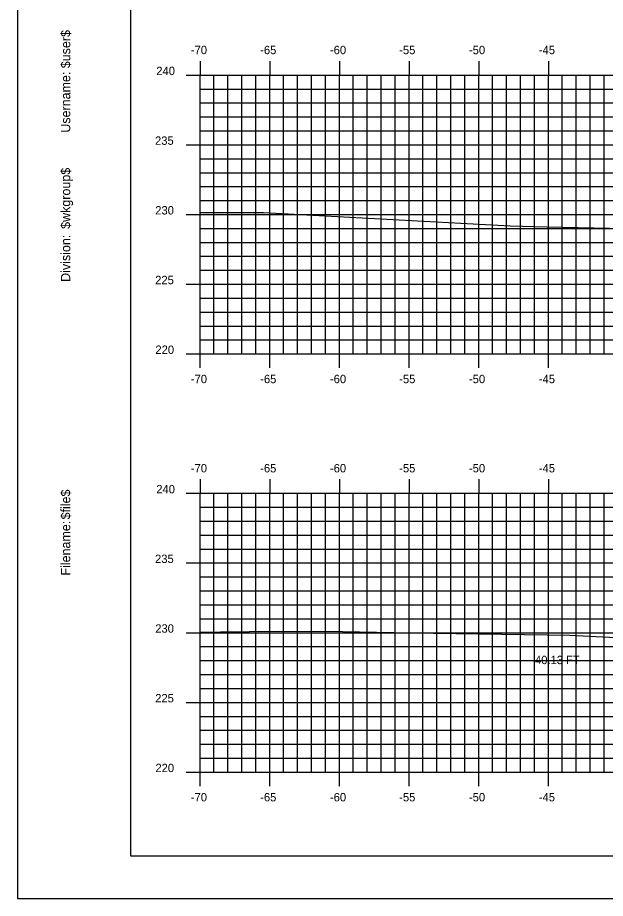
# Model space of a CAD drawing. Extents: x 1137211 to 1137381, y 608981 to 609091.
# Drawn here: x 1137210.8 to 1137253, y 608981.3 to 609044.5 of the extents above; entities that cross this region are included whole.
import ezdxf

# ---------------------------------------------------------------- set-up
doc = ezdxf.new("R2010")
doc.units = 0
for name, color, linetype in [('BORDER', 7, 'Continuous'), ('D_Text_Standard', 7, 'Continuous'), ('H_V ANNOTATION', 7, 'Continuous'), ('MAJOR', 7, 'Continuous'), ('MINOR', 7, 'Continuous'), ('PLOT BOUNDARY', 7, 'Continuous'), ('S_Roadway_Centerline', 7, 'Continuous')]:
    doc.layers.add(name, color=color, linetype=linetype)

msp = doc.modelspace()

# ---------------------------------------------------------------- linework, layer by layer
at = {"layer": 'BORDER'}
msp.add_lwpolyline([(1137218.897, 608984.335), (1137378.897, 608984.335), (1137378.897, 609089.335), (1137218.897, 609089.335)], close=True, dxfattribs=at)
at = {"layer": 'MAJOR'}
for p, q in [((1137223.896, 609041.337), (1137223.896, 609040.335)), ((1137228.896, 609041.337), (1137228.896, 609040.335)), ((1137233.896, 609041.337), (1137233.896, 609040.335)), ((1137238.896, 609041.337), (1137238.896, 609040.335)), ((1137243.896, 609041.337), (1137243.896, 609040.335)), ((1137248.896, 609041.337), (1137248.896, 609040.335)), ((1137222.894, 609040.335), (1137223.896, 609040.335)), ((1137223.896, 609040.335), (1137363.896, 609040.335)), ((1137223.896, 609020.335), (1137223.896, 609040.335)), ((1137223.896, 609020.335), (1137223.896, 609040.335)), ((1137223.896, 609040.335), (1137363.896, 609040.335)), ((1137228.896, 609020.335), (1137228.896, 609040.335)), ((1137233.896, 609020.335), (1137233.896, 609040.335)), ((1137238.896, 609020.335), (1137238.896, 609040.335)), ((1137243.896, 609020.335), (1137243.896, 609040.335)), ((1137248.896, 609020.335), (1137248.896, 609040.335)), ((1137222.894, 609035.335), (1137223.896, 609035.335)), ((1137223.896, 609035.335), (1137363.896, 609035.335)), ((1137222.894, 609030.335), (1137223.896, 609030.335)), ((1137223.896, 609030.335), (1137363.896, 609030.335)), ((1137222.894, 609025.335), (1137223.896, 609025.335)), ((1137223.896, 609025.335), (1137363.896, 609025.335)), ((1137222.894, 609020.335), (1137223.896, 609020.335)), ((1137223.896, 609020.335), (1137363.896, 609020.335)), ((1137223.896, 609020.335), (1137363.896, 609020.335)), ((1137223.896, 609019.333), (1137223.896, 609020.335)), ((1137228.896, 609019.333), (1137228.896, 609020.335)), ((1137233.896, 609019.333), (1137233.896, 609020.335)), ((1137238.896, 609019.333), (1137238.896, 609020.335)), ((1137243.896, 609019.333), (1137243.896, 609020.335)), ((1137248.896, 609019.333), (1137248.896, 609020.335)), ((1137223.896, 609011.337), (1137223.896, 609010.335)), ((1137228.896, 609011.337), (1137228.896, 609010.335)), ((1137233.896, 609011.337), (1137233.896, 609010.335)), ((1137238.896, 609011.337), (1137238.896, 609010.335)), ((1137243.896, 609011.337), (1137243.896, 609010.335)), ((1137248.896, 609011.337), (1137248.896, 609010.335)), ((1137222.894, 609010.335), (1137223.896, 609010.335)), ((1137223.896, 609010.335), (1137363.896, 609010.335)), ((1137223.896, 608990.335), (1137223.896, 609010.335)), ((1137223.896, 608990.335), (1137223.896, 609010.335)), ((1137223.896, 609010.335), (1137363.896, 609010.335)), ((1137228.896, 608990.335), (1137228.896, 609010.335)), ((1137233.896, 608990.335), (1137233.896, 609010.335)), ((1137238.896, 608990.335), (1137238.896, 609010.335)), ((1137243.896, 608990.335), (1137243.896, 609010.335)), ((1137248.896, 608990.335), (1137248.896, 609010.335)), ((1137222.894, 609005.335), (1137223.896, 609005.335)), ((1137223.896, 609005.335), (1137363.896, 609005.335)), ((1137222.894, 609000.335), (1137223.896, 609000.335)), ((1137223.896, 609000.335), (1137363.896, 609000.335)), ((1137222.894, 608995.335), (1137223.896, 608995.335)), ((1137223.896, 608995.335), (1137363.896, 608995.335)), ((1137222.894, 608990.335), (1137223.896, 608990.335)), ((1137223.896, 608990.335), (1137363.896, 608990.335)), ((1137223.896, 608990.335), (1137363.896, 608990.335)), ((1137223.896, 608989.333), (1137223.896, 608990.335)), ((1137228.896, 608989.333), (1137228.896, 608990.335)), ((1137233.896, 608989.333), (1137233.896, 608990.335)), ((1137238.896, 608989.333), (1137238.896, 608990.335)), ((1137243.896, 608989.333), (1137243.896, 608990.335)), ((1137248.896, 608989.333), (1137248.896, 608990.335))]:
    msp.add_line(p, q, dxfattribs=at)
at = {"layer": 'MINOR'}
for p, q in [((1137223.896, 609020.335), (1137223.896, 609040.335)), ((1137224.896, 609020.335), (1137224.896, 609040.335)), ((1137225.896, 609020.335), (1137225.896, 609040.335)), ((1137226.896, 609020.335), (1137226.896, 609040.335)), ((1137227.896, 609020.335), (1137227.896, 609040.335)), ((1137229.896, 609020.335), (1137229.896, 609040.335)), ((1137230.896, 609020.335), (1137230.896, 609040.335)), ((1137231.896, 609020.335), (1137231.896, 609040.335)), ((1137232.896, 609020.335), (1137232.896, 609040.335)), ((1137234.896, 609020.335), (1137234.896, 609040.335)), ((1137235.896, 609020.335), (1137235.896, 609040.335)), ((1137236.896, 609020.335), (1137236.896, 609040.335)), ((1137237.896, 609020.335), (1137237.896, 609040.335)), ((1137239.896, 609020.335), (1137239.896, 609040.335)), ((1137240.896, 609020.335), (1137240.896, 609040.335)), ((1137241.896, 609020.335), (1137241.896, 609040.335)), ((1137242.896, 609020.335), (1137242.896, 609040.335)), ((1137244.896, 609020.335), (1137244.896, 609040.335)), ((1137245.896, 609020.335), (1137245.896, 609040.335)), ((1137246.896, 609020.335), (1137246.896, 609040.335)), ((1137247.896, 609020.335), (1137247.896, 609040.335)), ((1137249.896, 609020.335), (1137249.896, 609040.335)), ((1137250.896, 609020.335), (1137250.896, 609040.335)), ((1137251.896, 609020.335), (1137251.896, 609040.335)), ((1137252.896, 609020.335), (1137252.896, 609040.335)), ((1137223.896, 609039.335), (1137363.896, 609039.335)), ((1137223.896, 609039.335), (1137224.898, 609039.335)), ((1137223.896, 609038.335), (1137363.896, 609038.335)), ((1137223.896, 609038.335), (1137224.898, 609038.335)), ((1137223.896, 609037.335), (1137363.896, 609037.335)), ((1137223.896, 609037.335), (1137224.898, 609037.335)), ((1137223.896, 609036.335), (1137363.896, 609036.335)), ((1137223.896, 609036.335), (1137224.898, 609036.335)), ((1137223.896, 609034.335), (1137363.896, 609034.335)), ((1137223.896, 609034.335), (1137224.898, 609034.335)), ((1137223.896, 609033.335), (1137363.896, 609033.335)), ((1137223.896, 609033.335), (1137224.898, 609033.335)), ((1137223.896, 609032.335), (1137363.896, 609032.335)), ((1137223.896, 609032.335), (1137224.898, 609032.335)), ((1137223.896, 609031.335), (1137363.896, 609031.335)), ((1137223.896, 609031.335), (1137224.898, 609031.335)), ((1137223.896, 609029.335), (1137363.896, 609029.335)), ((1137223.896, 609029.335), (1137224.898, 609029.335)), ((1137223.896, 609028.335), (1137363.896, 609028.335)), ((1137223.896, 609028.335), (1137224.898, 609028.335)), ((1137223.896, 609027.335), (1137363.896, 609027.335)), ((1137223.896, 609027.335), (1137224.898, 609027.335)), ((1137223.896, 609026.335), (1137363.896, 609026.335)), ((1137223.896, 609026.335), (1137224.898, 609026.335)), ((1137223.896, 609024.335), (1137363.896, 609024.335)), ((1137223.896, 609024.335), (1137224.898, 609024.335)), ((1137223.896, 609023.335), (1137363.896, 609023.335)), ((1137223.896, 609023.335), (1137224.898, 609023.335)), ((1137223.896, 609022.335), (1137363.896, 609022.335)), ((1137223.896, 609022.335), (1137224.898, 609022.335)), ((1137223.896, 609021.335), (1137363.896, 609021.335)), ((1137223.896, 609021.335), (1137224.898, 609021.335)), ((1137224.896, 608990.335), (1137224.896, 609010.335)), ((1137225.896, 608990.335), (1137225.896, 609010.335)), ((1137226.896, 608990.335), (1137226.896, 609010.335)), ((1137227.896, 608990.335), (1137227.896, 609010.335)), ((1137229.896, 608990.335), (1137229.896, 609010.335)), ((1137230.896, 608990.335), (1137230.896, 609010.335)), ((1137231.896, 608990.335), (1137231.896, 609010.335)), ((1137232.896, 608990.335), (1137232.896, 609010.335)), ((1137234.896, 608990.335), (1137234.896, 609010.335)), ((1137235.896, 608990.335), (1137235.896, 609010.335)), ((1137236.896, 608990.335), (1137236.896, 609010.335)), ((1137237.896, 608990.335), (1137237.896, 609010.335)), ((1137239.896, 608990.335), (1137239.896, 609010.335)), ((1137240.896, 608990.335), (1137240.896, 609010.335)), ((1137241.896, 608990.335), (1137241.896, 609010.335)), ((1137242.896, 608990.335), (1137242.896, 609010.335)), ((1137244.896, 608990.335), (1137244.896, 609010.335)), ((1137245.896, 608990.335), (1137245.896, 609010.335)), ((1137246.896, 608990.335), (1137246.896, 609010.335)), ((1137247.896, 608990.335), (1137247.896, 609010.335)), ((1137249.896, 608990.335), (1137249.896, 609010.335)), ((1137250.896, 608990.335), (1137250.896, 609010.335)), ((1137251.896, 608990.335), (1137251.896, 609010.335)), ((1137252.896, 608990.335), (1137252.896, 609010.335)), ((1137223.896, 609009.335), (1137363.896, 609009.335)), ((1137223.896, 609009.335), (1137224.898, 609009.335)), ((1137223.896, 609008.335), (1137363.896, 609008.335)), ((1137223.896, 609008.335), (1137224.898, 609008.335)), ((1137223.896, 609007.335), (1137363.896, 609007.335)), ((1137223.896, 609007.335), (1137224.898, 609007.335)), ((1137223.896, 609006.335), (1137363.896, 609006.335)), ((1137223.896, 609006.335), (1137224.898, 609006.335)), ((1137223.896, 609004.335), (1137363.896, 609004.335)), ((1137223.896, 609004.335), (1137224.898, 609004.335)), ((1137223.896, 609003.335), (1137363.896, 609003.335)), ((1137223.896, 609003.335), (1137224.898, 609003.335)), ((1137223.896, 609002.335), (1137363.896, 609002.335)), ((1137223.896, 609002.335), (1137224.898, 609002.335)), ((1137223.896, 609001.335), (1137363.896, 609001.335)), ((1137223.896, 609001.335), (1137224.898, 609001.335)), ((1137223.896, 608999.335), (1137363.896, 608999.335)), ((1137223.896, 608999.335), (1137224.898, 608999.335)), ((1137223.896, 608998.335), (1137363.896, 608998.335)), ((1137223.896, 608998.335), (1137224.898, 608998.335)), ((1137223.896, 608997.335), (1137363.896, 608997.335)), ((1137223.896, 608997.335), (1137224.898, 608997.335)), ((1137223.896, 608996.335), (1137363.896, 608996.335)), ((1137223.896, 608996.335), (1137224.898, 608996.335)), ((1137223.896, 608994.335), (1137363.896, 608994.335)), ((1137223.896, 608994.335), (1137224.898, 608994.335)), ((1137223.896, 608993.335), (1137363.896, 608993.335)), ((1137223.896, 608993.335), (1137224.898, 608993.335)), ((1137223.896, 608992.335), (1137363.896, 608992.335)), ((1137223.896, 608992.335), (1137224.898, 608992.335)), ((1137223.896, 608991.335), (1137363.896, 608991.335)), ((1137223.896, 608991.335), (1137224.898, 608991.335))]:
    msp.add_line(p, q, dxfattribs=at)
at = {"layer": 'PLOT BOUNDARY'}
msp.add_lwpolyline([(1137210.803, 608981.276), (1137380.803, 608981.276), (1137380.803, 609091.276), (1137210.803, 609091.276)], close=True, dxfattribs=at)
at = {"layer": 'S_Roadway_Centerline'}
for points in [[(1137223.896, 609030.475), (1137226.189, 609030.484), (1137228.443, 609030.476), (1137246.148, 609029.526), (1137248.798, 609029.444), (1137265.674, 609029.091), (1137267.433, 609029.009), (1137273.912, 609028.837), (1137276.343, 609028.953), (1137278.39, 609029.096), (1137282.861, 609029.317), (1137283.562, 609029.447), (1137287.936, 609029.577), (1137294.25, 609029.759), (1137299.127, 609029.829), (1137304.633, 609029.928), (1137312.395, 609030.077)], [(1137223.896, 609000.377), (1137225.357, 609000.391), (1137229.531, 609000.434), (1137234.116, 609000.419), (1137239.036, 609000.317), (1137250.446, 609000.16), (1137262.307, 608999.556), (1137270.041, 608999.249), (1137277.797, 608999.017), (1137279.478, 608999.069), (1137282.816, 608999.526), (1137284.833, 608999.711), (1137284.843, 608999.713), (1137285.155, 608999.73), (1137296.08, 609000.277), (1137301.744, 609000.456), (1137306.22, 609000.583), (1137313.681, 609000.675)]]:
    msp.add_lwpolyline(points, dxfattribs=at)

# ---------------------------------------------------------------- texts
at = {"layer": 'BORDER'}
for s, p in [('$user$', (1137214.581, 609040.827)), ('Username:', (1137214.581, 609036.203)), ('$wkgroup$', (1137214.581, 609029.305)), ('Division:', (1137214.581, 609025.501)), ('$file$', (1137214.581, 609008.461)), ('Filename:', (1137214.581, 609004.433))]:
    msp.add_text(s, height=0.6696, rotation=90, dxfattribs=at).set_placement(p)
at = {"layer": 'D_Text_Standard'}
msp.add_text('-40.13 FT', height=0.6, dxfattribs=at).set_placement((1137247.671, 608998.081))
at = {"layer": 'H_V ANNOTATION'}
for s, p in [('-70', (1137223.238, 609041.835)), ('-65', (1137228.214, 609041.835)), ('-60', (1137233.222, 609041.835)), ('-55', (1137238.192, 609041.835)), ('-50', (1137243.2, 609041.835)), ('-45', (1137248.214, 609041.835)), ('240', (1137220.758, 609040.335)), ('235', (1137220.667, 609035.335)), ('230', (1137220.683, 609030.335)), ('225', (1137220.678, 609025.335)), ('220', (1137220.694, 609020.335)), ('-70', (1137223.238, 609018.235)), ('-65', (1137228.214, 609018.235)), ('-60', (1137233.222, 609018.235)), ('-55', (1137238.192, 609018.235)), ('-50', (1137243.2, 609018.235)), ('-45', (1137248.214, 609018.235)), ('-70', (1137223.238, 609011.835)), ('-65', (1137228.214, 609011.835)), ('-60', (1137233.222, 609011.835)), ('-55', (1137238.192, 609011.835)), ('-50', (1137243.2, 609011.835)), ('-45', (1137248.214, 609011.835)), ('240', (1137220.758, 609010.335)), ('235', (1137220.667, 609005.335)), ('230', (1137220.683, 609000.335)), ('225', (1137220.678, 608995.335)), ('220', (1137220.694, 608990.335)), ('-70', (1137223.238, 608988.235)), ('-65', (1137228.214, 608988.235)), ('-60', (1137233.222, 608988.235)), ('-55', (1137238.192, 608988.235)), ('-50', (1137243.2, 608988.235)), ('-45', (1137248.214, 608988.235))]:
    msp.add_text(s, height=0.6, dxfattribs=at).set_placement(p)
at = {"layer": 'MAJOR'}
for p in [(1137223.892, 609020.335), (1137223.892, 608990.335)]:
    msp.add_text('-', height=0.006, dxfattribs=at).set_placement(p)

doc.saveas('drawing.dxf')
